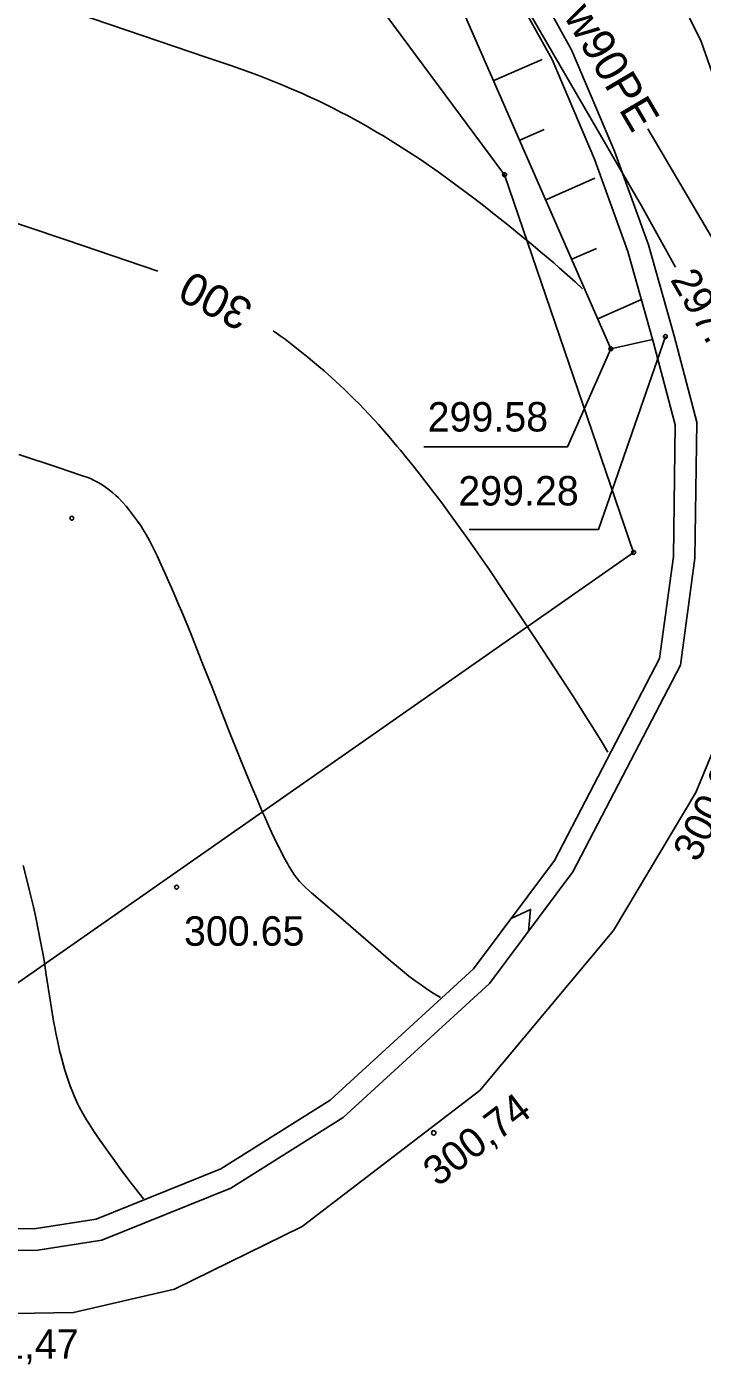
# Model space of a CAD drawing. Extents: x 7477803 to 7478145, y 5500698 to 5500984.
# Drawn here: x 7478010.69 to 7478026.29, y 5500810.72 to 5500841.6 of the extents above; entities that cross this region are included whole.
import ezdxf

# ---------------------------------------------------------------- set-up
doc = ezdxf.new("R2010")
doc.units = 0
for name, color, linetype in [('203-Punkt załamania granicy działki nie stabilizowany', 7, 'Continuous'), ('gr_dzialki', 7, 'Continuous'), ('gr_klasy', 7, 'Continuous'), ('jezdnia', 7, 'Continuous'), ('k', 7, 'Continuous'), ('k_rzedne', 7, 'Continuous'), ('pkt_wys', 7, 'Continuous'), ('rowy', 7, 'Continuous'), ('skarp_wypel', 7, 'Continuous'), ('skarpa_gora', 7, 'Continuous'), ('w', 7, 'Continuous'), ('w_opis', 7, 'Continuous'), ('warst_ciagla', 7, 'Continuous'), ('warst_opis', 7, 'Continuous'), ('warst_pogrub', 7, 'Continuous'), ('warst_przeryw', 7, 'Continuous')]:
    doc.layers.add(name, color=color, linetype=linetype)

# ---------------------------------------------------------------- blocks, each defined once
blk = doc.blocks.new('203')
blk.add_circle((0, 0), 0.045)
blk = doc.blocks.new('801_1')
at = {"layer": 'pkt_wys'}
blk.add_circle((0, 0), 0.045, dxfattribs=at)
blk.add_circle((0, 0), 0.045, dxfattribs=at)
blk = doc.blocks.new('801_5_2')
at = {"layer": 'pkt_wys'}
blk.add_circle((0, 0), 0.05, dxfattribs=at)
blk.add_circle((0, 0), 0.05, dxfattribs=at)

msp = doc.modelspace()

# ---------------------------------------------------------------- linework, layer by layer
at = {"layer": 'gr_dzialki'}
for points in [[(7478021.72, 5500838.18), (7478015.58, 5500846.47)], [(7478024.7, 5500829.46), (7478021.72, 5500838.18)], [(7478024.7, 5500829.46), (7478006.38, 5500816.66)]]:
    msp.add_lwpolyline(points, dxfattribs=at)
at = {"layer": 'gr_klasy'}
for points in [[(7478021.72, 5500838.18), (7478015.58, 5500846.47)], [(7478024.7, 5500829.46), (7478021.72, 5500838.18)], [(7478006.38, 5500816.66), (7478024.7, 5500829.46)]]:
    msp.add_lwpolyline(points, dxfattribs=at)
at = {"layer": 'jezdnia'}
msp.add_lwpolyline([(7478008.149, 5500811.845), (7478011.769, 5500811.909), (7478014.098, 5500812.451), (7478017.047, 5500813.895), (7478021.153, 5500817.039), (7478024.239, 5500820.732), (7478026.136, 5500823.914), (7478027.522, 5500827.266), (7478028.159, 5500830.207), (7478028.284, 5500834.367), (7478027.822, 5500836.806), (7478026.257, 5500841.255), (7478025.204, 5500843.403), (7478022.901, 5500846.211), (7478018.407, 5500849.956), (7478013.603, 5500853.721), (7478010.61, 5500855.711)], dxfattribs=at)
at = {"layer": 'k'}
for p, q in [((7478024.88, 5500837.459), (7478020.15, 5500845.626)), ((7478025.664, 5500836.042), (7478024.88, 5500837.459))]:
    msp.add_line(p, q, dxfattribs=at)
at = {"layer": 'pkt_wys'}
for points in [[(7478025.434, 5500834.444), (7478023.887, 5500829.991), (7478020.901, 5500829.987)], [(7478024.174, 5500834.162), (7478023.177, 5500831.898), (7478019.853, 5500831.894)]]:
    msp.add_lwpolyline(points, dxfattribs=at)
at = {"layer": 'rowy'}
for points in [[(7478022.21, 5500842.975), (7478023.266, 5500841.06), (7478024.262, 5500838.724), (7478025.045, 5500836.559), (7478025.636, 5500834.458), (7478026.16, 5500832.468), (7478026.117, 5500829.33), (7478025.782, 5500826.86), (7478023.298, 5500822.081), (7478021.376, 5500819.51), (7478017.996, 5500816.414), (7478015.397, 5500814.781), (7478012.422, 5500813.577), (7478010.943, 5500813.35), (7478008.556, 5500813.315), (7478003.273, 5500813.659), (7478001.759, 5500813.856), (7477999.58, 5500814.028), (7477997.292, 5500814.207), (7477990.382, 5500814.641), (7477980.361, 5500815.165)], [(7478021.784, 5500842.711), (7478022.816, 5500840.841), (7478023.796, 5500838.541), (7478024.569, 5500836.406), (7478025.154, 5500834.326), (7478025.659, 5500832.406), (7478025.618, 5500829.368), (7478025.298, 5500827.014), (7478022.873, 5500822.348), (7478021.004, 5500819.847), (7478017.692, 5500816.813), (7478015.168, 5500815.228), (7478012.289, 5500814.063), (7478010.902, 5500813.85), (7478008.569, 5500813.815), (7478003.321, 5500814.157), (7478001.811, 5500814.354), (7477999.619, 5500814.526), (7477997.327, 5500814.706), (7477990.411, 5500815.14), (7477980.39, 5500815.664)], [(7478022.273, 5500820.71), (7478022.323, 5500821.216), (7478021.873, 5500821.009)]]:
    msp.add_lwpolyline(points, dxfattribs=at)
at = {"layer": 'skarp_wypel'}
for p, q in [((7478021.47, 5500840.353), (7478022.587, 5500840.841)), ((7478022.07, 5500838.978), (7478022.633, 5500839.224)), ((7478022.671, 5500837.604), (7478023.807, 5500838.1)), ((7478023.271, 5500836.229), (7478023.844, 5500836.479)), ((7478023.872, 5500834.855), (7478024.881, 5500835.296)), ((7478025.139, 5500834.378), (7478024.174, 5500834.162))]:
    msp.add_line(p, q, dxfattribs=at)
at = {"layer": 'skarpa_gora'}
msp.add_lwpolyline([(7478024.174, 5500834.162), (7478020.445, 5500842.698), (7478019.361, 5500843.679)], dxfattribs=at)
at = {"layer": 'w'}
msp.add_lwpolyline([(7478027.498, 5500835.049), (7478025.026, 5500839.239)], dxfattribs=at)
at = {"layer": 'warst_ciagla'}
msp.add_lwpolyline([(7478010.604, 5500822.229), (7478010.705, 5500821.84), (7478010.752, 5500821.649), (7478010.812, 5500821.398), (7478010.841, 5500821.275), (7478010.895, 5500821.03), (7478010.962, 5500820.711), (7478010.993, 5500820.554), (7478011.057, 5500820.207), (7478011.086, 5500820.038), (7478011.139, 5500819.707), (7478011.234, 5500819.077), (7478011.282, 5500818.782), (7478011.307, 5500818.639), (7478011.341, 5500818.454), (7478011.359, 5500818.363), (7478011.396, 5500818.188), (7478011.447, 5500817.962), (7478011.474, 5500817.854), (7478011.537, 5500817.62), (7478011.569, 5500817.508), (7478011.614, 5500817.364), (7478011.637, 5500817.295), (7478011.684, 5500817.16), (7478011.749, 5500816.99), (7478011.782, 5500816.909), (7478011.86, 5500816.737), (7478011.9, 5500816.656), (7478011.983, 5500816.502), (7478012.069, 5500816.358), (7478012.127, 5500816.265), (7478012.247, 5500816.084), (7478012.385, 5500815.881), (7478012.575, 5500815.61), (7478012.672, 5500815.474), (7478012.821, 5500815.269), (7478013.025, 5500814.994), (7478013.13, 5500814.856), (7478013.383, 5500814.531)], dxfattribs=at)
at = {"layer": 'warst_pogrub'}
for points in [[(7478013.715, 5500835.955), (7478011.612, 5500836.666), (7478008.739, 5500837.631)], [(7478024.107, 5500824.849), (7478023.972, 5500825.072), (7478023.758, 5500825.418), (7478023.636, 5500825.612), (7478023.294, 5500826.148), (7478022.746, 5500826.991), (7478022.432, 5500827.468), (7478021.976, 5500828.156), (7478021.737, 5500828.514), (7478021.369, 5500829.057), (7478020.997, 5500829.594), (7478020.813, 5500829.856), (7478020.63, 5500830.111), (7478020.39, 5500830.441), (7478020.271, 5500830.601), (7478020.036, 5500830.912), (7478019.729, 5500831.309), (7478019.578, 5500831.499), (7478019.465, 5500831.639), (7478019.317, 5500831.819), (7478019.243, 5500831.908), (7478019.049, 5500832.137), (7478018.952, 5500832.249), (7478018.807, 5500832.412), (7478018.59, 5500832.65), (7478018.37, 5500832.88), (7478018.258, 5500832.993), (7478018.031, 5500833.215), (7478017.915, 5500833.325), (7478017.736, 5500833.488), (7478017.553, 5500833.65), (7478017.43, 5500833.755), (7478017.186, 5500833.959), (7478017.068, 5500834.055), (7478016.846, 5500834.231), (7478016.651, 5500834.381), (7478016.54, 5500834.464), (7478016.477, 5500834.509), (7478016.38, 5500834.576)]]:
    msp.add_lwpolyline(points, dxfattribs=at)
at = {"layer": 'warst_przeryw'}
for points in [[(7478011.019, 5500842.184), (7478012.992, 5500841.519), (7478014.847, 5500840.889), (7478015.375, 5500840.708), (7478015.636, 5500840.616), (7478016.024, 5500840.475), (7478016.41, 5500840.326), (7478016.603, 5500840.248), (7478016.795, 5500840.167), (7478017.052, 5500840.055), (7478017.18, 5500839.996), (7478017.436, 5500839.876), (7478017.778, 5500839.707), (7478017.948, 5500839.62), (7478018.076, 5500839.552), (7478018.247, 5500839.46), (7478018.332, 5500839.413), (7478018.523, 5500839.306), (7478018.779, 5500839.158), (7478018.906, 5500839.082), (7478019.162, 5500838.926), (7478019.501, 5500838.71), (7478019.671, 5500838.598), (7478019.799, 5500838.513), (7478019.968, 5500838.398), (7478020.053, 5500838.339), (7478020.244, 5500838.205), (7478020.626, 5500837.927), (7478021.011, 5500837.638), (7478021.27, 5500837.438), (7478021.444, 5500837.302), (7478021.796, 5500837.023), (7478022.154, 5500836.734), (7478022.332, 5500836.587), (7478022.598, 5500836.365), (7478022.858, 5500836.143), (7478022.985, 5500836.032), (7478023.23, 5500835.812), (7478023.348, 5500835.704), (7478023.517, 5500835.543)], [(7478020.239, 5500819.181), (7478020.069, 5500819.286), (7478019.963, 5500819.354), (7478019.768, 5500819.487), (7478019.679, 5500819.551), (7478019.513, 5500819.677), (7478019.363, 5500819.798), (7478019.271, 5500819.875), (7478019.098, 5500820.023), (7478017.938, 5500821.024), (7478017.261, 5500821.603), (7478017.129, 5500821.718), (7478017.07, 5500821.773), (7478017.013, 5500821.831), (7478016.985, 5500821.862), (7478016.929, 5500821.931), (7478016.9, 5500821.97), (7478016.855, 5500822.034), (7478016.808, 5500822.106), (7478016.742, 5500822.216), (7478016.706, 5500822.277), (7478016.633, 5500822.411), (7478016.528, 5500822.613), (7478016.473, 5500822.725), (7478016.341, 5500823.001), (7478016.271, 5500823.152), (7478016.175, 5500823.368), (7478016.124, 5500823.481), (7478016.021, 5500823.72), (7478015.876, 5500824.062), (7478015.801, 5500824.244), (7478015.624, 5500824.678), (7478015.342, 5500825.386), (7478014.958, 5500826.365), (7478014.772, 5500826.837), (7478014.512, 5500827.487), (7478014.404, 5500827.753), (7478014.267, 5500828.086), (7478014.202, 5500828.242), (7478014.062, 5500828.572), (7478013.872, 5500829.005), (7478013.795, 5500829.175), (7478013.7, 5500829.379), (7478013.655, 5500829.471), (7478013.562, 5500829.656), (7478013.52, 5500829.737), (7478013.442, 5500829.877), (7478013.371, 5500829.994), (7478013.326, 5500830.062), (7478013.243, 5500830.183), (7478013.152, 5500830.307), (7478013.037, 5500830.457), (7478012.981, 5500830.525), (7478012.9, 5500830.619), (7478012.797, 5500830.728), (7478012.747, 5500830.775), (7478012.675, 5500830.839), (7478012.629, 5500830.876), (7478012.539, 5500830.943), (7478012.474, 5500830.988), (7478012.39, 5500831.042), (7478012.349, 5500831.067), (7478012.289, 5500831.1), (7478012.212, 5500831.139), (7478012.175, 5500831.156), (7478012.118, 5500831.178), (7478011.951, 5500831.237), (7478011.415, 5500831.417), (7478010.501, 5500831.723)]]:
    msp.add_lwpolyline(points, dxfattribs=at)

# ---------------------------------------------------------------- block references
at = {"layer": '203-Punkt załamania granicy działki nie stabilizowany'}
for p in [(7478021.72, 5500838.18), (7478024.7, 5500829.46)]:
    msp.add_blockref('203', p, dxfattribs=at)
at = {"layer": 'pkt_wys', "rotation": 0.0626175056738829}
for name, p in [('801_1', (7478025.434, 5500834.444)), ('801_1', (7478024.174, 5500834.162)), ('801_1', (7478011.729, 5500830.249)), ('801_1', (7478014.148, 5500821.731)), ('801_5_2', (7478020.084, 5500816.058))]:
    msp.add_blockref(name, p, dxfattribs=at)

# ---------------------------------------------------------------- texts
at = {"layer": 'k_rzedne'}
msp.add_text('297.32', height=0.68, rotation=300.0796, dxfattribs=at).set_placement((7478025.534, 5500835.759))
at = {"layer": 'pkt_wys'}
for s, rotation, p in [('299.58', 0.0626, (7478019.945, 5500832.249)), ('299.28', 0.0626, (7478020.653, 5500830.541)), ('300,05', 63.6643, (7478026.186, 5500822.281)), ('300.65', 0.0626, (7478014.319, 5500820.377)), ('300,74', 37.2787, (7478020.174, 5500814.797)), ('301,47', 0.0626, (7478009.106, 5500810.84))]:
    msp.add_text(s, height=0.68, rotation=rotation, dxfattribs=at).set_placement(p)
at = {"layer": 'w_opis'}
msp.add_text('w90PE', height=0.75, rotation=300.5443, dxfattribs=at).set_placement((7478023.07, 5500841.852))
at = {"layer": 'warst_opis'}
msp.add_text('300', height=0.75, rotation=152.6382, dxfattribs=at).set_placement((7478015.962, 5500835.215))

doc.saveas('drawing.dxf')
